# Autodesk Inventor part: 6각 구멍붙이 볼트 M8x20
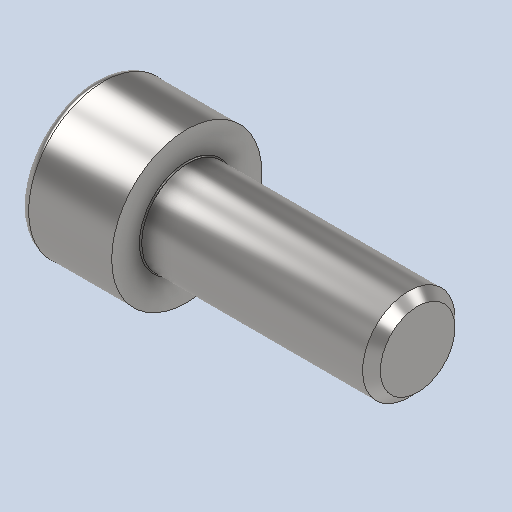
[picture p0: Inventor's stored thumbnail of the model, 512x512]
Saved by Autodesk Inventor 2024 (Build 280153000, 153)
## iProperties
Created: 2025-06
Part Number: 6각 구멍붙이 볼트 M8x20
Material: 강철, 연강
Description: 6각머리 태핑 나사
Document SubType Name: Modeling
Designer: 11
Density: 7.85 g/cm^3
Appearance: 기본값
Author: jhkim
Sending System: Autodesk Inventor 2026
Preprocessor: ST-DEVELOPER v20.1
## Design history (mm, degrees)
node "6각 구멍붙이 볼트 M8x201"
node "솔리드1"
body "Solid1"
